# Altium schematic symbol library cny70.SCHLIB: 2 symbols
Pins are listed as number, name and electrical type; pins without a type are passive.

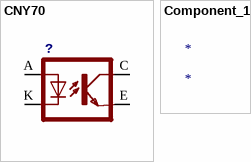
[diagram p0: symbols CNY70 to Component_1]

## CNY70
designator ?
footprint cny70 (Footprint not found)
pins: A, C COL, E EMI, K C

## Component_1
designator *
